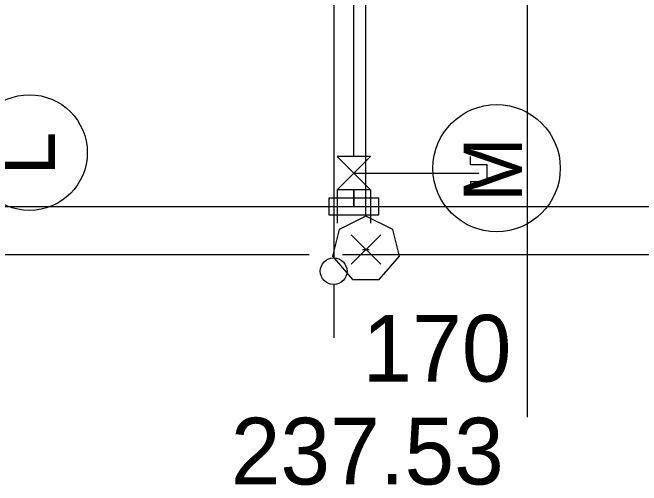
# Model space of a CAD drawing. Extents: x -264222 to -263592, y -1242345 to -1242048.
# Drawn here: x -263841.78 to -263832.36, y -1242254.32 to -1242247.23 of the extents above; entities that cross this region are included whole.
import ezdxf

# ---------------------------------------------------------------- set-up
doc = ezdxf.new("R2010")
doc.units = 0
for name, color, linetype in [('BOD_CISLO', 7, 'Continuous'), ('BOD_SYMBOL', 7, 'Continuous'), ('BOD_VYSKA', 7, 'Continuous'), ('HESCON_OSI_STAVBY_KFA', 7, 'Continuous'), ('KFA_2D_SITUACIA_DSP', 7, 'Continuous'), ('KFA_SO_62-1_VO_LAMPY_MERANE', 7, 'Continuous'), ('KFA_SO_62-1_VO_TRASA_KABLOV_PROJEKT', 7, 'Continuous')]:
    doc.layers.add(name, color=color, linetype=linetype)

msp = doc.modelspace()

# ---------------------------------------------------------------- linework, layer by layer
at = {"layer": 'BOD_SYMBOL'}
for p, q in [((-263836.706, -1242251.005), (-263836.264, -1242250.563)), ((-263836.264, -1242251.005), (-263836.706, -1242250.563))]:
    msp.add_line(p, q, dxfattribs=at)
at = {"layer": 'HESCON_OSI_STAVBY_KFA'}
for centre, radius in [((-263841.5276, -1242249.3311), 0.867), ((-263834.5276, -1242249.5647), 0.9542)]:
    msp.add_circle(centre, radius, dxfattribs=at)
at = {"layer": 'KFA_2D_SITUACIA_DSP'}
for p, q in [((-263836.9678, -1242235.7572), (-263836.9691, -1242250.9091)), ((-263836.6677, -1242249.3899), (-263836.6678, -1242235.7572)), ((-263834.0678, -1242241.1322), (-263834.0678, -1242253.2979)), ((-263836.9178, -1242249.8899), (-263836.4177, -1242249.3899)), ((-263836.4177, -1242249.3899), (-263836.9177, -1242249.3899)), ((-263836.9177, -1242249.3899), (-263836.4178, -1242249.8899)), ((-263834.9178, -1242249.5149), (-263834.9178, -1242249.3899)), ((-263834.6678, -1242249.5148), (-263834.9178, -1242249.5149)), ((-263834.6678, -1242249.7648), (-263834.6678, -1242249.5148)), ((-263836.6678, -1242249.6399), (-263834.7928, -1242249.6398)), ((-263834.9178, -1242249.7649), (-263834.6678, -1242249.7648)), ((-263834.9178, -1242249.7649), (-263834.9178, -1242249.8899)), ((-263836.4178, -1242249.8899), (-263836.9178, -1242249.8899)), ((-263836.9178, -1242249.8899), (-263836.9178, -1242250.3899)), ((-263836.6678, -1242250.1399), (-263836.6678, -1242249.8899)), ((-263836.6678, -1242249.8899), (-263836.6678, -1242250.1399)), ((-263836.4178, -1242249.8899), (-263836.4178, -1242250.3899)), ((-263836.2928, -1242250.0149), (-263837.0428, -1242250.0149)), ((-263837.0428, -1242250.0149), (-263837.0428, -1242250.2649)), ((-263836.2928, -1242250.2649), (-263836.2928, -1242250.0149)), ((-263924.1428, -1242250.1399), (-263788.1428, -1242250.1399)), ((-263837.0428, -1242250.2649), (-263836.2928, -1242250.2649)), ((-263836.9692, -1242251.3091), (-263836.9692, -1242252.1091))]:
    msp.add_line(p, q, dxfattribs=at)
msp.add_circle((-263836.9692, -1242251.1091), 0.2, dxfattribs=at)
at = {"layer": 'KFA_SO_62-1_VO_LAMPY_MERANE'}
for p, q in [((-263836.535, -1242250.784), (-263836.435, -1242250.784)), ((-263836.485, -1242250.784), (-263836.485, -1242250.784))]:
    msp.add_line(p, q, dxfattribs=at)
msp.add_lwpolyline([(-263836.485, -1242250.284), (-263836.885, -1242250.484), (-263836.985, -1242250.884), (-263836.685, -1242251.234), (-263836.285, -1242251.234), (-263835.985, -1242250.884), (-263836.085, -1242250.484), (-263836.485, -1242250.284), (-263836.485, -1242246.284), (-263832.585, -1242245.384)], dxfattribs=at)
at = {"layer": 'KFA_SO_62-1_VO_TRASA_KABLOV_PROJEKT'}
for p, q in [((-263837.3378, -1242250.8628), (-263856.3378, -1242250.8628)), ((-263817.8378, -1242250.8628), (-263836.8378, -1242250.8628))]:
    msp.add_line(p, q, dxfattribs=at)

# ---------------------------------------------------------------- texts
at = {"layer": 'BOD_CISLO'}
msp.add_text('170', height=1, dxfattribs=at).set_placement((-263836.5364, -1242252.7638))
at = {"layer": 'BOD_VYSKA'}
msp.add_text('237.53', height=1, dxfattribs=at).set_placement((-263838.5102, -1242254.306))
at = {"layer": 'HESCON_OSI_STAVBY_KFA'}
for s, p in [('L', (-263841.147, -1242249.671)), ('M', (-263834.147, -1242250.0738))]:
    msp.add_text(s, height=0.875, rotation=90, dxfattribs=at).set_placement(p)

doc.saveas('drawing.dxf')
